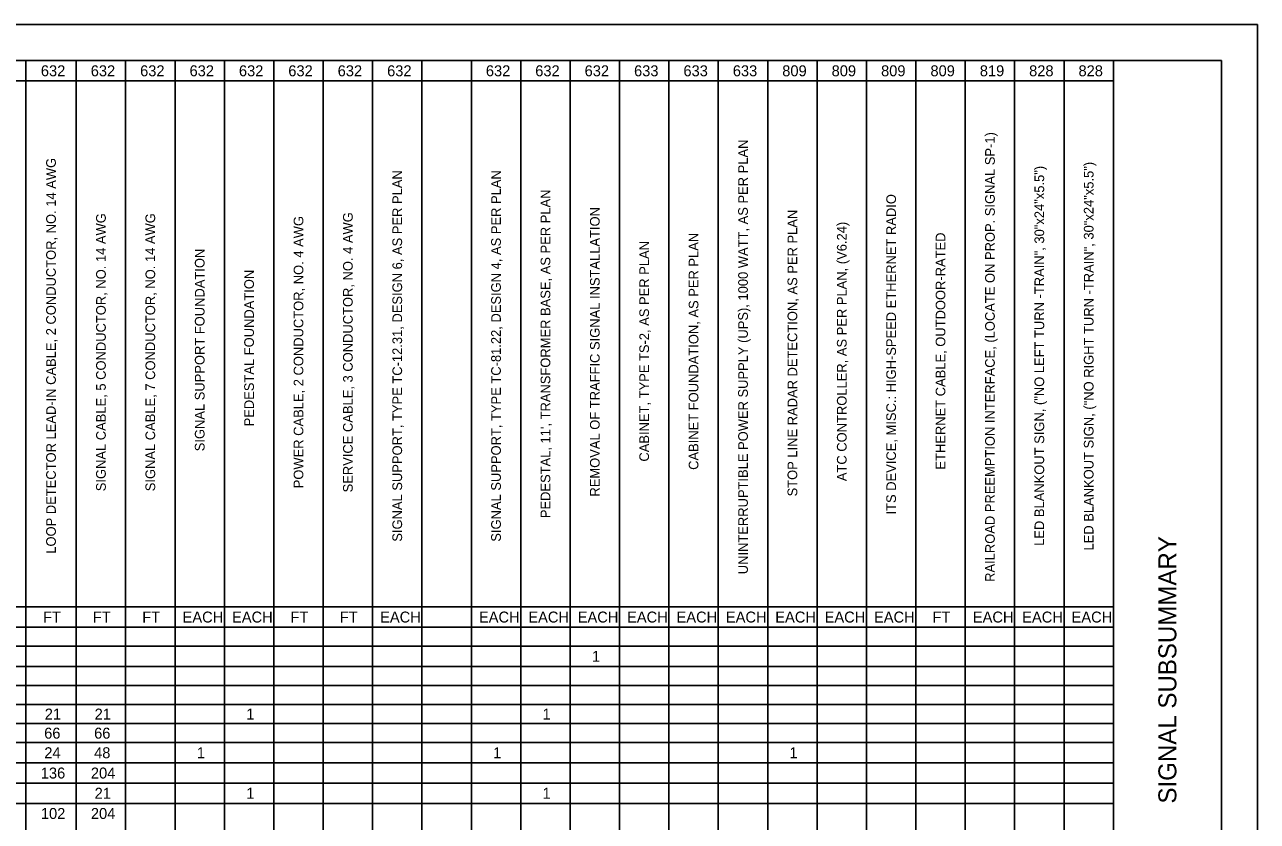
# Model space of a CAD drawing. Extents: x -0.2 to 34, y 0 to 22.
# Drawn here: x 16.87 to 34, y 10.93 to 22 of the extents above; entities that cross this region are included whole.
import ezdxf

# ---------------------------------------------------------------- set-up
doc = ezdxf.new("R2010")
doc.units = 0
for name, color, linetype in [('DV_X_Property_Line', 7, 'Continuous'), ('RW_X_CL', 7, 'Continuous'), ('SC_Scratch1', 7, 'Continuous'), ('SV_X_Mon_Cells_Found', 7, 'Continuous')]:
    doc.layers.add(name, color=color, linetype=linetype)

msp = doc.modelspace()

# ---------------------------------------------------------------- linework, layer by layer
at = {"layer": 'DV_X_Property_Line'}
msp.add_line((32, 0.5), (32, 21.5), dxfattribs=at)
msp.add_lwpolyline([(1.5, 21.5), (33.5, 21.5), (33.5, 0.5), (1.5, 0.5)], close=True, dxfattribs=at)
at = {"layer": 'RW_X_CL'}
msp.add_lwpolyline([(0, 0), (34, 0), (34, 22), (0, 22)], close=True, dxfattribs=at)
at = {"layer": 'SV_X_Mon_Cells_Found'}
for p, q in [((1.5, 21.5), (32, 21.5)), ((16.889, 21.5), (16.889, 0.5)), ((17.59, 21.5), (17.59, 0.5)), ((18.276, 21.5), (18.276, 0.5)), ((18.962, 21.5), (18.962, 0.5)), ((19.648, 21.5), (19.648, 0.5)), ((20.334, 21.5), (20.334, 0.5)), ((21.021, 21.5), (21.021, 0.5)), ((21.707, 21.5), (21.707, 0.5)), ((22.393, 21.5), (22.393, 0.5)), ((23.079, 21.5), (23.079, 0.5)), ((23.765, 21.5), (23.765, 0.5)), ((24.452, 21.5), (24.452, 0.5)), ((25.138, 21.5), (25.138, 0.5)), ((25.824, 21.5), (25.824, 0.5)), ((26.51, 21.5), (26.51, 0.5)), ((27.197, 21.5), (27.197, 0.5)), ((27.883, 21.5), (27.883, 0.5)), ((28.569, 21.5), (28.569, 0.5)), ((29.255, 21.5), (29.255, 0.5)), ((29.941, 21.5), (29.941, 0.5)), ((30.628, 21.5), (30.628, 0.5)), ((31.314, 21.5), (31.314, 0.5)), ((32, 21.5), (32, 0.5)), ((6.596, 21.219), (32, 21.219)), ((6.596, 13.91), (32, 13.91)), ((1.5, 13.629), (32, 13.629)), ((1.5, 13.365), (32, 13.365)), ((1.5, 13.083), (32, 13.083)), ((1.5, 12.819), (32, 12.819)), ((1.5, 12.554), (32, 12.554)), ((1.5, 12.29), (32, 12.29)), ((1.5, 12.025), (32, 12.025)), ((1.5, 11.744), (32, 11.744)), ((1.5, 11.463), (32, 11.463)), ((1.5, 11.182), (32, 11.182))]:
    msp.add_line(p, q, dxfattribs=at)

# ---------------------------------------------------------------- texts
at = {"layer": 'SC_Scratch1'}
msp.add_text('SIGNAL SUBSUMMARY', height=0.25, rotation=90, dxfattribs=at).set_placement((32.875, 11.179))
at = {"layer": 'SV_X_Mon_Cells_Found'}
for s, height, p in [('632', 0.1521, (17.098, 21.283)), ('632', 0.1521, (17.791, 21.283)), ('632', 0.1521, (18.477, 21.283)), ('632', 0.1521, (19.164, 21.283)), ('632', 0.1521, (19.85, 21.283)), ('632', 0.1521, (20.536, 21.283)), ('632', 0.1521, (21.222, 21.283)), ('632', 0.1521, (21.909, 21.283)), ('632', 0.1521, (23.281, 21.283)), ('632', 0.1521, (23.967, 21.283)), ('632', 0.1521, (24.653, 21.283)), ('633', 0.1521, (25.34, 21.283)), ('633', 0.1521, (26.026, 21.283)), ('633', 0.1521, (26.712, 21.283)), ('809', 0.1521, (27.399, 21.283)), ('809', 0.1521, (28.085, 21.283)), ('809', 0.1521, (28.772, 21.283)), ('809', 0.1521, (29.458, 21.283)), ('819', 0.1521, (30.144, 21.283)), ('828', 0.1521, (30.829, 21.283)), ('828', 0.1521, (31.515, 21.283)), ('FT', 0.1521, (17.128, 13.694)), ('FT', 0.1521, (17.821, 13.694)), ('FT', 0.1521, (18.507, 13.694)), ('EACH', 0.1521, (19.067, 13.694)), ('EACH', 0.1521, (19.754, 13.694)), ('FT', 0.1521, (20.566, 13.694)), ('FT', 0.1521, (21.252, 13.694)), ('EACH', 0.1521, (21.812, 13.694)), ('EACH', 0.1521, (23.185, 13.694)), ('EACH', 0.1521, (23.871, 13.694)), ('EACH', 0.1521, (24.557, 13.694)), ('EACH', 0.1521, (25.243, 13.694)), ('EACH', 0.1521, (25.93, 13.694)), ('EACH', 0.1521, (26.616, 13.694)), ('EACH', 0.1521, (27.302, 13.694)), ('EACH', 0.1521, (27.988, 13.694)), ('EACH', 0.1521, (28.674, 13.694)), ('FT', 0.1521, (29.487, 13.694)), ('EACH', 0.1521, (30.047, 13.694)), ('EACH', 0.1521, (30.733, 13.694)), ('EACH', 0.1521, (31.419, 13.694)), ('1', 0.152, (24.754, 13.148)), ('21', 0.1521, (17.152, 12.346)), ('21', 0.1521, (17.845, 12.346)), ('1', 0.152, (19.951, 12.346)), ('1', 0.152, (24.068, 12.346)), ('66', 0.1521, (17.144, 12.081)), ('66', 0.1521, (17.838, 12.081)), ('24', 0.1521, (17.146, 11.809)), ('48', 0.1521, (17.838, 11.809)), ('1', 0.152, (19.265, 11.809)), ('1', 0.152, (23.382, 11.809)), ('1', 0.152, (27.499, 11.809)), ('136', 0.1521, (17.097, 11.527)), ('204', 0.1521, (17.793, 11.527)), ('21', 0.1521, (17.845, 11.246)), ('1', 0.152, (19.951, 11.246)), ('1', 0.152, (24.068, 11.246)), ('102', 0.1521, (17.098, 10.965)), ('204', 0.1521, (17.793, 10.965))]:
    msp.add_text(s, height=height, dxfattribs=at).set_placement(p)
for s, p in [('UNINTERRUPTIBLE POWER SUPPLY (UPS), 1000 WATT, AS PER PLAN', (26.921, 14.365)), ('RAILROAD PREEMPTION INTERFACE, (LOCATE ON PROP. SIGNAL SP-1)', (30.352, 14.259)), ('LOOP DETECTOR LEAD-IN CABLE, 2 CONDUCTOR, NO. 14 AWG', (17.306, 14.65)), ('LED BLANKOUT SIGN, ("NO RIGHT TURN -TRAIN", 30"x24"x5.5")', (31.724, 14.695)), ('SIGNAL SUPPORT, TYPE TC-12.31, DESIGN 6, AS PER PLAN', (22.117, 14.817)), ('SIGNAL SUPPORT, TYPE TC-81.22, DESIGN 4, AS PER PLAN', (23.489, 14.817)), ('LED BLANKOUT SIGN, ("NO LEFT TURN -TRAIN", 30"x24"x5.5")', (31.038, 14.759)), ("PEDESTAL, 11', TRANSFORMER BASE, AS PER PLAN", (24.176, 15.144)), ('ITS DEVICE, MISC.: HIGH-SPEED ETHERNET RADIO', (28.979, 15.195)), ('SIGNAL CABLE, 5 CONDUCTOR, NO. 14 AWG', (18, 15.518)), ('SIGNAL CABLE, 7 CONDUCTOR, NO. 14 AWG', (18.686, 15.518)), ('SERVICE CABLE, 3 CONDUCTOR, NO. 4 AWG', (21.431, 15.502)), ('REMOVAL OF TRAFFIC SIGNAL INSTALLATION', (24.862, 15.444)), ('STOP LINE RADAR DETECTION, AS PER PLAN', (27.607, 15.446)), ('POWER CABLE, 2 CONDUCTOR, NO. 4 AWG', (20.745, 15.559)), ('ATC CONTROLLER, AS PER PLAN, (V6.24)', (28.293, 15.658)), ('CABINET FOUNDATION, AS PER PLAN', (26.234, 15.815)), ('ETHERNET CABLE, OUTDOOR-RATED', (29.665, 15.819)), ('SIGNAL SUPPORT FOUNDATION', (19.372, 16.073)), ('CABINET, TYPE TS-2, AS PER PLAN', (25.548, 15.93)), ('PEDESTAL FOUNDATION', (20.058, 16.419))]:
    msp.add_text(s, height=0.13432, rotation=90, dxfattribs=at).set_placement(p)

doc.saveas('drawing.dxf')
